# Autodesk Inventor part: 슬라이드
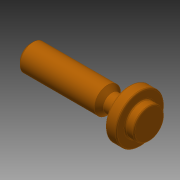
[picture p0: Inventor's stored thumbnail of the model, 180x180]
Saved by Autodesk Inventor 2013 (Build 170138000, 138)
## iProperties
Company: 한국ATC센터
Created: 2015-12
Part Number: 슬라이드
Document SubType Name: Modeling
Designer: mdu
Density: 7.86 g/cm^3
Mass: 55.1178 g
Surface Area: 28.7656 cm^2
Volume: 7.01244 cm^3
Material: 강철, 연강
Author: mdu
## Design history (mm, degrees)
sketch "스케치1"
  geometry: L1 (-25, 0)-(25, 0); L2 (25, 0)-(25, 11); L3 (25, 11)-(20, 11); L4 (20, 11)-(20, 4); L5 (20, 4)-(12, 4); L6 (12, 4)-(10, 6); L7 (10, 6)-(-25, 6); L8 (-25, 6)-(-25, 0); 1 further point
  constraints: 16 end point, 4 parallel, 2 midpoint, 2 perpendicular, 1 horizontal
  dimensions: "d0" = 50 distance of L1.start L1.end; "d1" = 12 diameter of L7 L1; "d2" = 22 diameter of L3 L1; "d3" = 5 distance of L2.end L3.end; "d4" = 8 diameter of L5 L1; "d5" = 135 deg angle of L6 L5; "d6" = 15 distance from line of L2 L6.end
revolve "회전1" sketch "스케치1" stored, may be unused: angle "d7" = 90 deg
chamfer "모따기1" distance "d8" = 1; stored, may be unused: second distance "d9" = 2, angle "d10" = 45 deg
fillet "모깎기1" dims "d11" = 0.5
sketch "스케치5"
  geometry: C1 r 7 at (0, 0); 1 further point
  constraints: 1 centre point, 1 coincident
  dimensions: "d23" = 14 diameter of C1
extrude "돌출2" join sketch "스케치5" distance "d24" = 4; taper "d25" = 0 deg
fillet "모깎기3" dims "d26" = 0.5
node "솔리드1"
